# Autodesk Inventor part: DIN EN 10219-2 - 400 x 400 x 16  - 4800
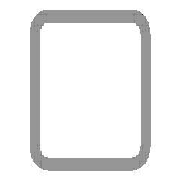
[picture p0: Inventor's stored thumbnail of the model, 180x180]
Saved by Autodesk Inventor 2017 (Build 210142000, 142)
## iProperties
IsCustomPart: 1
Created: 2017-11
Part Number: DIN EN 10219-2 - 400 x 400 x 16  - 4800
Material: Steel, Mild
Description: Cold formed welded structural hollow sections of non-alloy and fine grain structural steel
Document SubType Name: Modeling
Standard: DIN
Designer: iusti
Standard Revision: 2006-07
Standards Organization: DIN
Language: en-US
Size Designation: 400 x 400 x 16
Categories: <MemberInstance><Categories><Category DisplayName="Structural Shapes" InternalName="089c4875-fa83-4c05-b084-43b9cc11f5ed" Mnemonic="GRDR"><CategoryParameter Dis
Stock Number: 400 x 400 x 16
Density: 7.85 g/cm^3
Appearance: Semi-Polished
Mass: 884622 g
Surface Area: 141333 cm^2
Volume: 112691 cm^3
_CCFamilyMember: 142
_CCFamilyDisplayName: DIN EN 10219-2 (Square Hollow Section - Cold Formed) - Cold formed welded structural hollow sections of non-alloy and fine grain structural steel
_FrameMemberDoc: Frame Member File
_Version: 15.0.0
_GetPNFromCC: 1
G_L: 4800.000 mm
G_W: 400.000 mm
G_H: 400.000 mm
+38AB50A9-5FEF-434A-B58F-2C43C3F5CDA6+CUTDETAIL1: Cut
Author: iusti
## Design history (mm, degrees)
node "Start plane"
node "End plane"
sketch "Sketch"
  geometry: L1 (-200, -152)-(-200, 152); L2 (-152, 200)-(152, 200); L3 (200, 152)-(200, -152); L4 (152, -200)-(-152, -200); L5 (-152, 184)-(152, 184); L6 (184, 152)-(184, -152); L7 (152, -184)-(-152, -184); L8 (-184, -152)-(-184, 152); L9 (0, 293.918)-(0, -293.918) reference; L10 (-293.918, 0)-(293.918, 0) reference; A1 r 48 centre (-152, -152) between (-200, -152) and (-152, -200); A2 r 48 centre (-152, 152) between (-152, 200) and (-200, 152); A3 r 48 centre (152, 152) between (200, 152) and (152, 200); A4 r 48 centre (152, -152) between (152, -200) and (200, -152); A5 r 32 centre (-152, 152) between (-152, 184) and (-184, 152); A6 r 32 centre (152, 152) between (184, 152) and (152, 184); A7 r 32 centre (152, -152) between (152, -184) and (184, -152); A8 r 32 centre (-152, -152) between (-184, -152) and (-152, -184)
  constraints: 16 end point, 16 point on circle, 8 centre point, 8 tangent, 4 parallel, 3 equal radius, 2 perpendicular, 7 other
  dimensions: "d7" = 48 radius of A1 (= G_IR); "d10" = 400 distance between parallel lines of L2 L4 (= G_H); "d11" = 400 distance between parallel lines of L1 L3 (= G_W); "d12" = 16 distance between parallel lines of L3 L6 (= G_T); "d15" = 200 distance between parallel lines of L2 L10 (= 0.5 x d10); "d16" = 200 distance between parallel lines of L9 L3 (= 0.5 x d11)
extrude "Body" new body sketch "Sketch" stored distance "d3" = 4800 (= G_L); taper "d4" = 0 deg
node "Driven Length"
  sketch "Sketch3"
    geometry: L1 (0, 0)-(10, 0) reference
    constraints: 2 end point, 1 horizontal
  workplane "Work Plane3"
  sketch "Sketch4"
    geometry: L1 (-2, 0)-(12, 0) reference; L2 (-2, 4800)-(12, 4800) reference
    dimensions: "d18" = 4800 distance between parallel lines of L1 L2 (derived)
workplane "Work Plane4"
split "Split1"
body "Solid1"
other parameters: "G_W" = 400 [user parameter; used in 1 equation term], "G_H" = 400 [user parameter; used in 1 equation term], "G_T" = 16 [user parameter; used in 1 equation term], "G_IR" = 48 [user parameter; used in 1 equation term], "G_L" = 4800 (= d18) [user parameter; used in 1 equation term], "G_OFFSET_START" = 0 [user parameter; used in 1 equation term], "d13" = 0 (computed from G_OFFSET_START), "d17" = 90 deg
